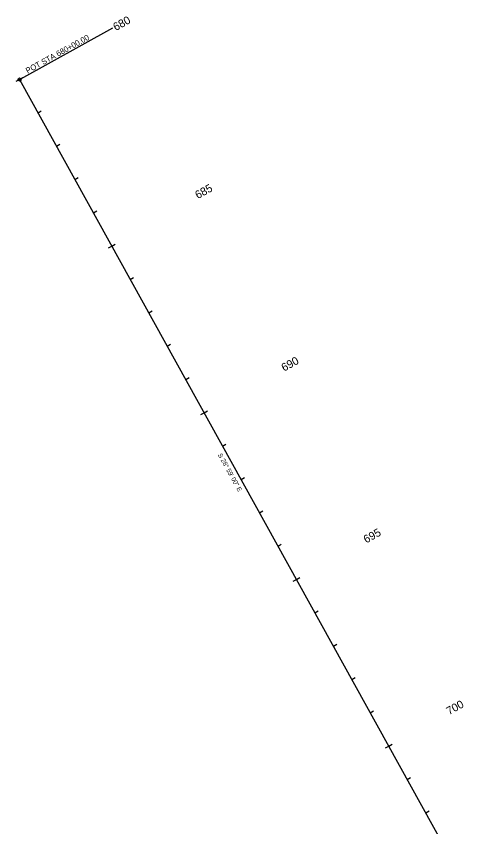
# Model space of a CAD drawing. Extents: x 2819977 to 2827606, y 113942 to 150283.
# Drawn here: x 2820492 to 2821682, y 148156 to 150283 of the extents above; entities that cross this region are included whole.
import ezdxf

# ---------------------------------------------------------------- set-up
doc = ezdxf.new("R2010")
doc.units = 0
for name, color, linetype in [('Level 63', 7, 'Continuous'), ('Roadway-Safety', 7, 'Continuous'), ('Utility-Power', 7, 'Continuous')]:
    doc.layers.add(name, color=color, linetype=linetype)

msp = doc.modelspace()

# ---------------------------------------------------------------- linework, layer by layer
at = {"layer": 'Level 63'}
msp.add_circle((2820500.6, 150117), 4, dxfattribs=at)
at = {"layer": 'Roadway-Safety'}
msp.add_line((2820504.1, 150119), (2820745.5, 150252.7), dxfattribs=at)
at = {"layer": 'Utility-Power'}
for p, q in [((2820491.9, 150112.2), (2820500.6, 150117)), ((2820500.6, 150117), (2820509.4, 150121.9)), ((2820500.6, 150117), (2821682.4, 147983.6)), ((2820549.1, 150029.5), (2820557.8, 150034.4)), ((2820597.5, 149942.1), (2820606.3, 149946.9)), ((2820646, 149854.6), (2820654.7, 149859.4)), ((2820694.4, 149767.1), (2820703.2, 149772)), ((2820734.1, 149674.8), (2820742.9, 149679.6)), ((2820742.9, 149679.6), (2820751.6, 149684.5)), ((2820791.3, 149592.2), (2820800.1, 149597)), ((2820839.8, 149504.7), (2820848.5, 149509.5)), ((2820888.3, 149417.2), (2820897, 149422.1)), ((2820936.7, 149329.7), (2820945.5, 149334.6)), ((2820976.4, 149237.4), (2820985.2, 149242.3)), ((2820985.2, 149242.3), (2820993.9, 149247.1)), ((2821033.6, 149154.8), (2821042.4, 149159.6)), ((2821082.1, 149067.3), (2821090.8, 149072.2)), ((2821130.5, 148979.8), (2821139.3, 148984.7)), ((2821179, 148892.4), (2821187.7, 148897.2)), ((2821227.4, 148804.9), (2821236.2, 148809.7)), ((2821218.7, 148800), (2821227.4, 148804.9)), ((2821275.9, 148717.4), (2821284.6, 148722.3)), ((2821324.4, 148629.9), (2821333.1, 148634.8)), ((2821372.8, 148542.5), (2821381.6, 148547.3)), ((2821421.3, 148455), (2821430, 148459.8)), ((2821461, 148362.7), (2821469.7, 148367.5)), ((2821469.7, 148367.5), (2821478.5, 148372.3)), ((2821518.2, 148280), (2821526.9, 148284.9)), ((2821566.6, 148192.6), (2821575.4, 148197.4))]:
    msp.add_line(p, q, dxfattribs=at)

# ---------------------------------------------------------------- texts
at = {"layer": 'Roadway-Safety'}
for s, height, rotation, p in [('POT STA 680+00.00', 15, 28.9835, (2820521.9, 150132.2)), ('S 28%%d 59\' 00" E', 12, 298.9835, (2821020.8, 149131.6))]:
    msp.add_text(s, height=height, rotation=rotation, dxfattribs=at).set_placement(p)
at = {"layer": 'Utility-Power'}
for s, p in [(' 680', (2820746.5, 150240.1)), (' 685', (2820961.7, 149799.1)), (' 690', (2821188.1, 149346.2)), (' 695', (2821403.7, 148895.4)), (' 700', (2821621.2, 148444.7))]:
    msp.add_text(s, height=21, rotation=28.9835, dxfattribs=at).set_placement(p)

doc.saveas('drawing.dxf')
